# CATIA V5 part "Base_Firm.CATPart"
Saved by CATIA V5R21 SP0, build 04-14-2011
Part number: Base_Firm
Bounding box of the stored display mesh (mm): x -238.95 to 250, y -200 to 200, z -3 to 0
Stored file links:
  C:\Users\Administrator\Desktop\arm\Arm_Detailed_Design_Assembly_Manu\Base_Firm.CATPart
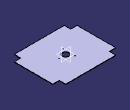
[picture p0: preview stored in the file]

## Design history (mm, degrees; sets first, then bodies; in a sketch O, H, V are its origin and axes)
Body1 (main body)
  DatumSurface1
  DatumCurve1
  Sketch1 on face of DatumSurface1, origin (0, 0, 0), H (1, 0, 0), V (0, -1, 0)
    line L1 (-188.95, 200) -> (200, 200)
    line L2 (250, 150) -> (250, -150)
    line L3 (200, -200) -> (-188.95, -200)
    line L4 (-238.95, -150) -> (-238.95, 150)
    reference projected circle E1 centre (0, 0) radius 11.05 from edge of DatumCurve1
    construction line L5 (563.0896, 0) -> (-645.9571, 0)
    point P1 (563.0896, 0)
    construction line L6 (0, 468.1874) -> (0, -510.8524)
    point P3 (0, 468.1874)
    circle A1 centre (52.5, 0) radius 2.5
    point P5 (52.5, 0)
    point P6 (55, 0)
    circle A2 centre (-26.25, 45.4663) radius 2.5
    circle A3 centre (-26.25, -45.4663) radius 2.5
    construction line L7 (-480.3696, 150) -> (758.441, 150)
    construction line L8 (-480.3696, -150) -> (706.0298, -150)
    construction line L9 (200, 293.5955) -> (200, -539.0408)
    axis line L10 (-188.95, -500.9048) -> (-188.95, 411.1816)
    point P17 (-188.95, -200)
    point P18 (-238.95, -150)
    point P19 (200, -200)
    point P20 (250, -150)
    point P21 (250, 150)
    point P22 (200, 200)
    point P23 (-188.95, 200)
    point P24 (-238.95, 150)
    line L11 (-238.95, 150) -> (-188.95, 150)
    point P25 (-188.95, 150)
    line L12 (-188.95, 150) -> (-188.95, 200)
    line L13 (200, 200) -> (200, 150)
    point P26 (200, 150)
    line L14 (200, 150) -> (250, 150)
    line L15 (200, -200) -> (200, -150)
    point P27 (200, -150)
    line L16 (200, -150) -> (250, -150)
    line L17 (-238.95, -150) -> (-188.95, -150)
    point P28 (-188.95, -150)
    line L18 (-188.95, -150) -> (-188.95, -200)
    circle A4 centre (0, 0) radius 25
    distance L4 E1 = 250
    distance V L2 = 250
    distance L1 H = 200
    distance H L3 = 200
    radius A1 = 2.5
    distance P5 L6 = 52.5
    distance L1 L7 = 50
    distance L8 L3 = 50
    distance L9 L2 = 50
    distance L10 L4 = 50
    radius A4 = 25
    horizontal: L1 H, L3 H, L5 H, L7 H, L8 H, L11 H, L14 H, L16 H, L17 H
    vertical: L2 V, L4 V, L6 V, L9 V, L10 V, L12 V, L13 V, L15 V, L18 V
    coincidence: P1 H, P3 V, P5 L5, A1 P6, P6 L5, L10 P17, L8 P18, L9 P19, L8 P20, L7 P21, L9 P22, L10 P23, L7 P24, P25 L10, P26 L7, P27 L8, P28 L10
  Pad1: profile Sketch1, direction (0, 0, -1), length 3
